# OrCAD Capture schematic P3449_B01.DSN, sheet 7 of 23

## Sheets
7 0016_HDMI: size Custom
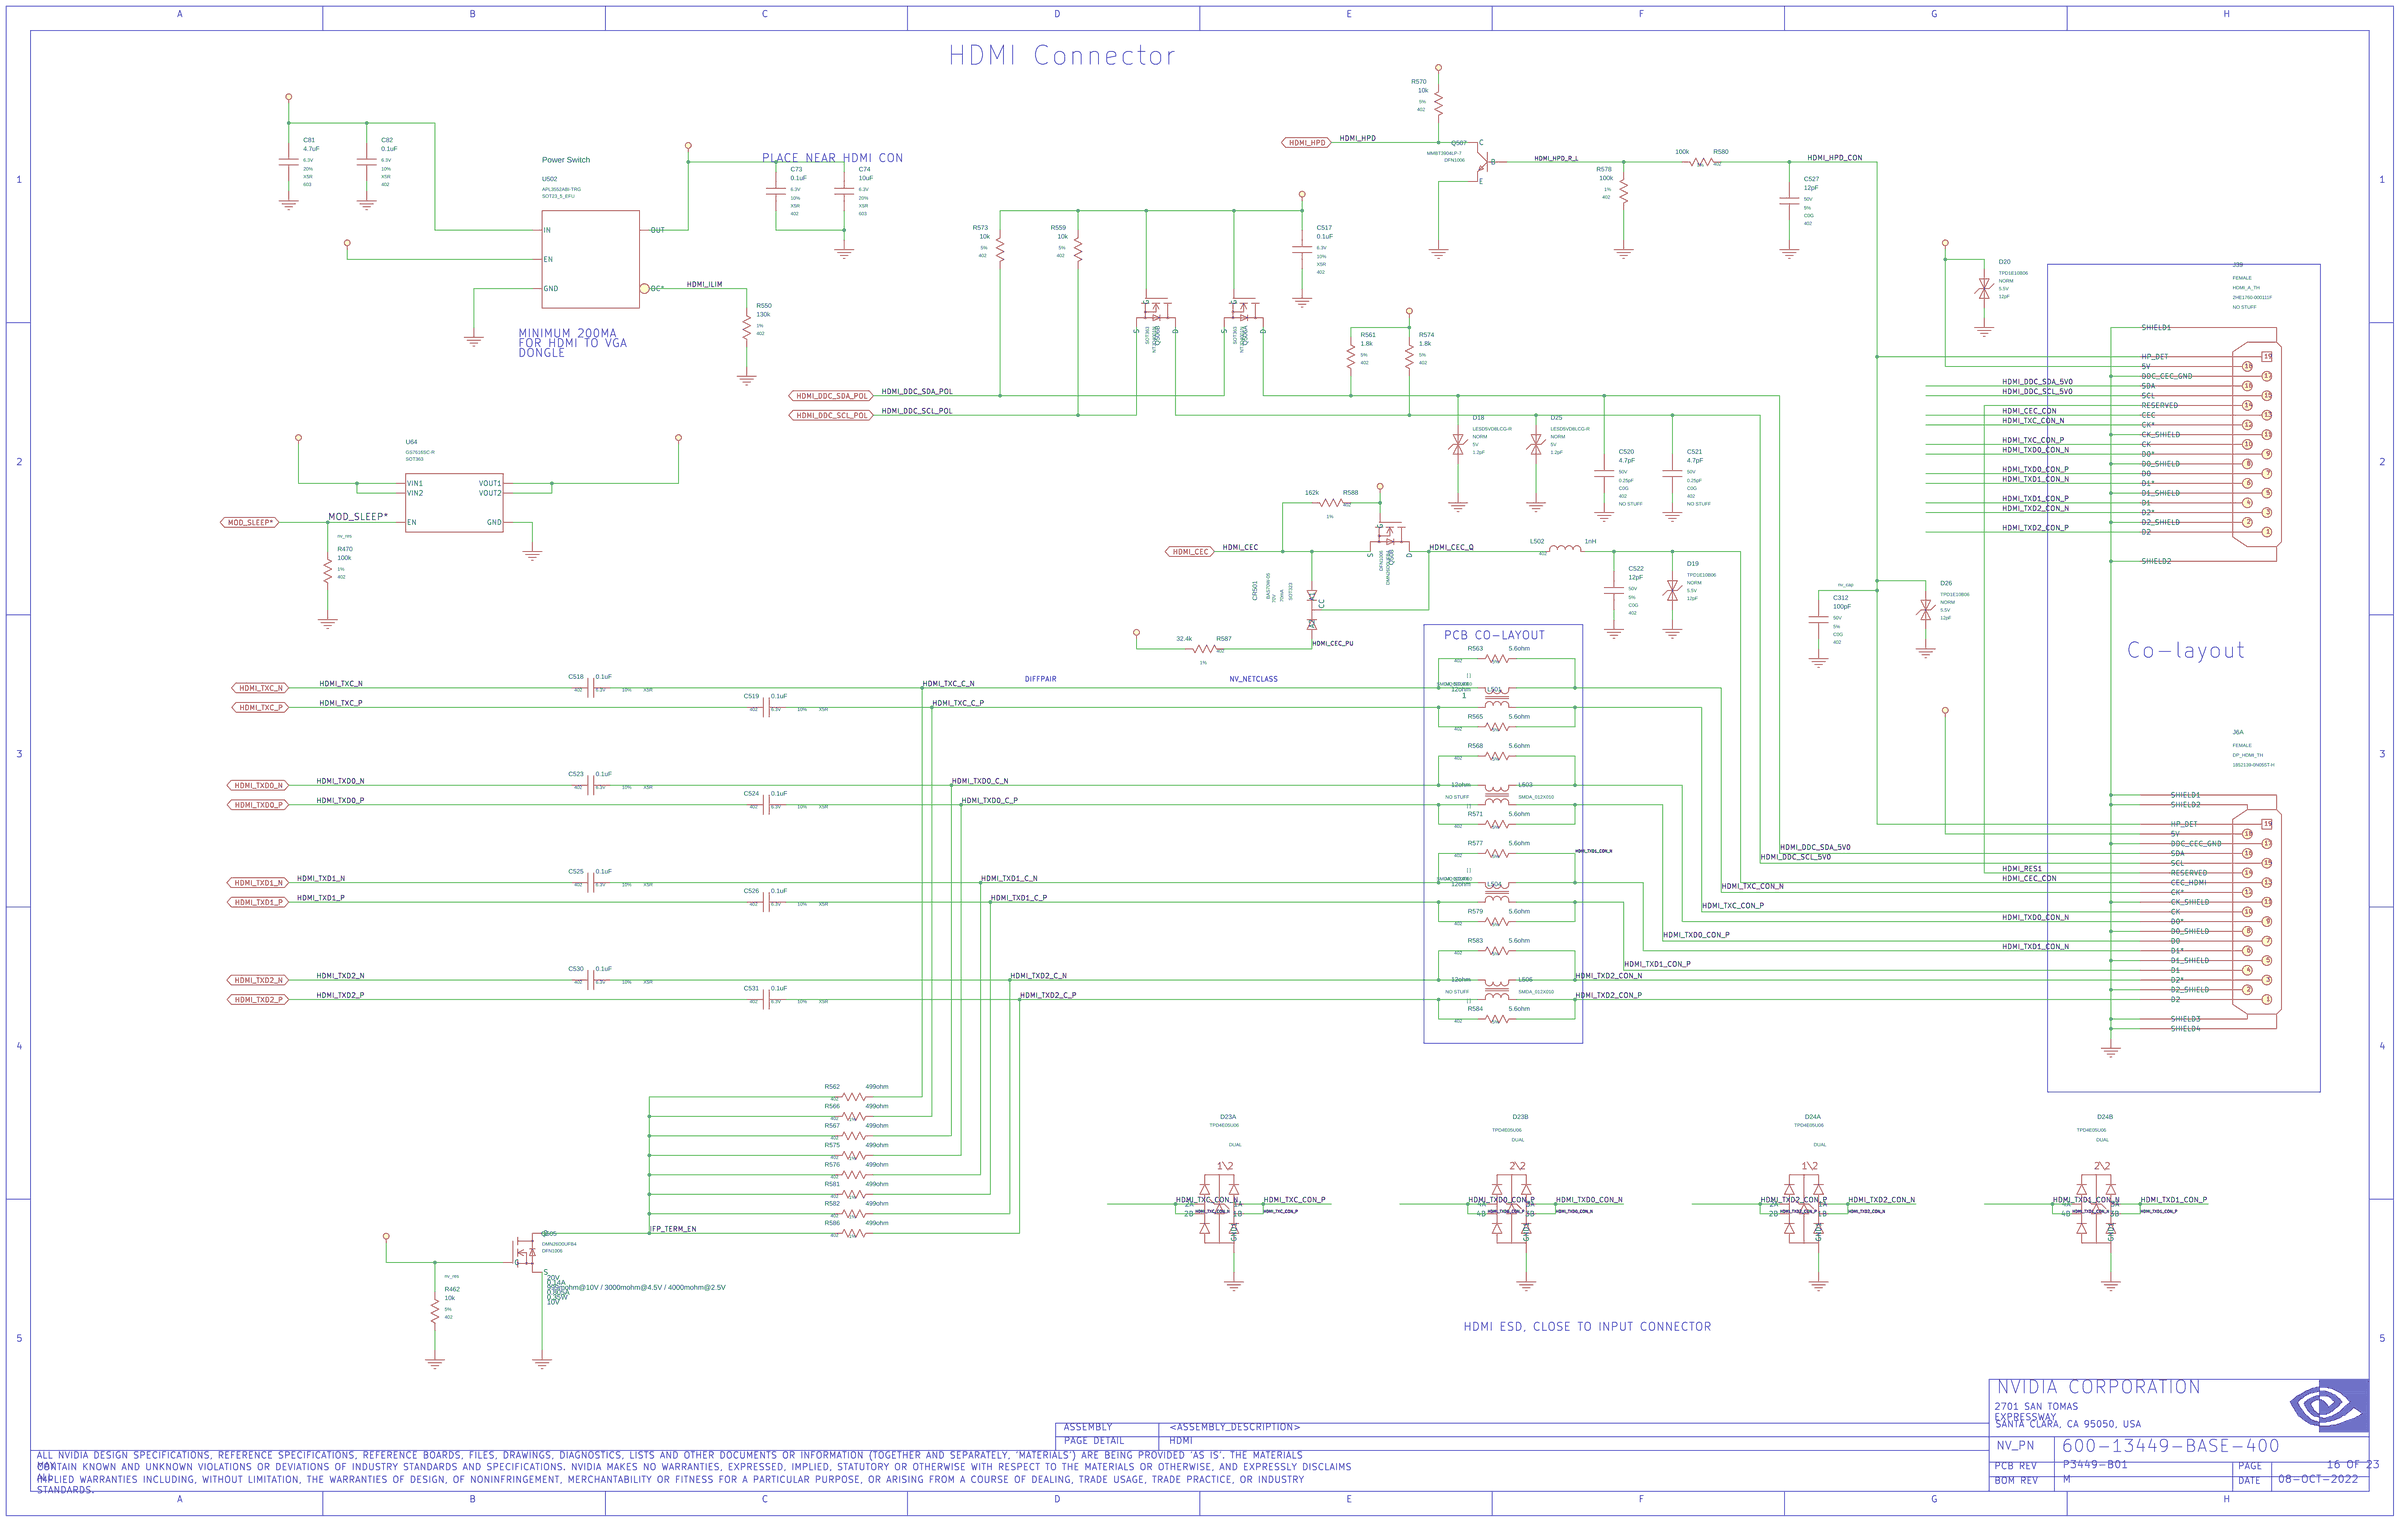
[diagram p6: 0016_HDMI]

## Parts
sheet 0016_HDMI
C73  0.1uF  [402]
C74  10uF  [603]
C81  4.7uF  [603]
C82  0.1uF  [402]
C312  100pF  [402]
C517  0.1uF  [402]
C518  0.1uF  [402]
C519  0.1uF  [402]
C520  4.7pF  [402]
C521  4.7pF  [402]
C522  12pF  [402]
C523  0.1uF  [402]
C524  0.1uF  [402]
C525  0.1uF  [402]
C526  0.1uF  [402]
C527  12pF  [402]
C530  0.1uF  [402]
C531  0.1uF  [402]
CR501  D_3PIN_CC  [SOT323]
D18  D_ESD  [DIODE_SMD_010X060]
D19  D_ESD  [DIODE_SMD_010X060]
D20  D_ESD  [DIODE_SMD_010X060]
D23  D_ESD_DIFFPAIR  [TSLP10_P050_025X010]  (sections A,B)
D24  D_ESD_DIFFPAIR  [TSLP10_P050_025X010]  (sections A,B)
D25  D_ESD  [DIODE_SMD_010X060]
D26  D_ESD  [DIODE_SMD_010X060]
J39  CON_HDMI  [CON_HDMI_019_TH_RA_F_P015]
L501  12ohm  [IND_NONRKO_SMD_012X010]
L502  1nH  [IND_SMD_0402]
L503  12ohm  [IND_NONRKO_SMD_012X010]
L504  12ohm  [IND_NONRKO_SMD_012X010]
L506  12ohm  [IND_NONRKO_SMD_012X010]
Q505  Q_FET_N_ENH  [DFET_003_SMD_010X006_B]
Q506  Q_FET_N_ENH  [SC70_6]  (sections A,B)
Q507  Q_NPN  [DFET_003_SMD_010X006_B]
Q508  Q_FET_N_ENH  [DFET_003_SMD_010X006_B]
R462  10k  [402]
R470  100k  [402]
R550  130k  [402]
R559  10k  [402]
R561  1.8k  [402]
R562  499ohm  [402]
R563  5.6ohm  [402]
R565  5.6ohm  [402]
R566  499ohm  [402]
R567  499ohm  [402]
R568  5.6ohm  [402]
R570  10k  [402]
R571  5.6ohm  [402]
R573  10k  [402]
R574  1.8k  [402]
R575  499ohm  [402]
R576  499ohm  [402]
R577  5.6ohm  [402]
R578  100k  [402]
R579  5.6ohm  [402]
R580  100k  [402]
R581  499ohm  [402]
R582  499ohm  [402]
R583  5.6ohm  [402]
R584  5.6ohm  [402]
R586  499ohm  [402]
R587  32.4k  [402]
R588  162k  [402]
U64  U_SW_LOAD  [SC70_6]
U502  U_PWR_SW_UL  [SOT23_5]
sheet 0017_DisplayPort
J6  CON_HDMI_DISPLAYPORT  [CON_HDMI_019_DP_020_TH_RA_F_181X180_B]  (sections A,B)

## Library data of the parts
C73 = C#1: ASSEMBLY: HDMI; CDS_LIB: discrete; CDS_PART_NAME: C_0402-0.1UF,X5R,10%,6.3V,039-0007-000; CDS_PHYS_PART_NAME: C_0402-0.1UF,X5R,10%,6.3V,039-0007-000-0.1UF,039-0007-000; CDS_SEC: 1; CHIPS_PART_NAME: C; DEVICE_TYPENAME: C_0402-01UFX5R1063V039-0007-000-01UF039-0007-000; DRAWING: @P3449_B01_LIB.P3449_B01(SCH_1):PAGE16; ESL: N/A; ESR: N/A; MAT: X5R; MAX_VOLTAGE: 6.3V; NV_PN: 039-0007-000; PATH: I332; PHYS_PAGE: 16; ROT: 0; SEC: 1; SIGNAL_MODEL: nv_cap; TOL: 10%; VER: 1; XY: (-8200,6650)
C74 = C#1: ASSEMBLY: HDMI; CDS_LIB: discrete; CDS_PART_NAME: C_0603-10UF,X5R,20%,6.3V,039-0135-000; CDS_PHYS_PART_NAME: C_0603-10UF,X5R,20%,6.3V,039-0135-000-039-0135-000,10UF; CDS_SEC: 1; CHIPS_PART_NAME: C; DEVICE_TYPENAME: C_0603-10UFX5R2063V039-0135-000-039-0135-00010UF; DRAWING: @P3449_B01_LIB.P3449_B01(SCH_1):PAGE16; ESL: N/A; ESR: N/A; MAT: X5R; MAX_VOLTAGE: 6.3V; NV_PN: 039-0135-000; PATH: I340; PHYS_PAGE: 16; ROT: 0; SEC: 1; SIGNAL_MODEL: nv_cap; TOL: 20%; VER: 1; XY: (-7850,6650)
C81 = C#1: ASSEMBLY: HDMI; CDS_LIB: discrete; CDS_PART_NAME: C_0603-4.7UF,X5R,20%,6.3V,032-0886-000; CDS_PHYS_PART_NAME: C_0603-4.7UF,X5R,20%,6.3V,032-0886-000-032-0886-000,4.7UF; CDS_SEC: 1; CHIPS_PART_NAME: C; DEVICE_TYPENAME: C_0603-47UFX5R2063V032-0886-000-032-0886-00047UF; DRAWING: @P3449_B01_LIB.P3449_B01(SCH_1):PAGE16; MAT: X5R; MAX_VOLTAGE: 6.3V; NV_PN: 032-0886-000; PATH: I266; PHYS_PAGE: 16; ROT: 0; SEC: 1; SIGNAL_MODEL: nv_cap; TOL: 20%; VER: 1; XY: (-10700,6800)
C82 = C#1: ASSEMBLY: HDMI; CDS_LIB: discrete; CDS_PART_NAME: C_0402-0.1UF,X5R,10%,6.3V,039-0007-000; CDS_PHYS_PART_NAME: C_0402-0.1UF,X5R,10%,6.3V,039-0007-000-0.1UF,039-0007-000; CDS_SEC: 1; CHIPS_PART_NAME: C; DEVICE_TYPENAME: C_0402-01UFX5R1063V039-0007-000-01UF039-0007-000; DRAWING: @P3449_B01_LIB.P3449_B01(SCH_1):PAGE16; ESL: N/A; ESR: N/A; MAT: X5R; MAX_VOLTAGE: 6.3V; NV_PN: 039-0007-000; PATH: I271; PHYS_PAGE: 16; ROT: 0; SEC: 1; SIGNAL_MODEL: nv_cap; TOL: 10%; VER: 1; XY: (-10300,6800)
C312 = C#1: ASSEMBLY: HDMI; CDS_LIB: discrete; CDS_PART_NAME: C_0402-100PF,C0G,5%,50V,035-0012-000; CDS_PHYS_PART_NAME: C_0402-100PF,C0G,5%,50V,035-0012-000-035-0012-000,100PF; CDS_SEC: 1; CHIPS_PART_NAME: C; DEVICE_TYPENAME: C_0402-100PFC0G550V035-0012-000-035-0012-000100PF; DRAWING: @P3449_B01_LIB.P3449_B01(SCH_1):PAGE16; MAT: C0G; MAX_VOLTAGE: 50V; NV_PN: 035-0012-000; PATH: I415; PHYS_PAGE: 16; ROT: 0; SEC: 1; SIGNAL_MODEL: nv_cap; TOL: 5%; VER: 1; XY: (-2850,4450)
C517 = C#1: ASSEMBLY: HDMI; CDS_LIB: discrete; CDS_PART_NAME: C_0402-0.1UF,X5R,10%,6.3V,039-0007-000; CDS_PHYS_PART_NAME: C_0402-0.1UF,X5R,10%,6.3V,039-0007-000-0.1UF,039-0007-000; CDS_SEC: 1; CHIPS_PART_NAME: C; DEVICE_TYPENAME: C_0402-01UFX5R1063V039-0007-000-01UF039-0007-000; DRAWING: @P3449_B01_LIB.P3449_B01(SCH_1):PAGE16; ESL: N/A; ESR: N/A; MAT: X5R; MAX_VOLTAGE: 6.3V; NV_PN: 039-0007-000; PATH: I315; PHYS_PAGE: 16; ROT: 0; SEC: 1; SIGNAL_MODEL: nv_cap; TOL: 10%; VER: 1; XY: (-5500,6350)
C518 = C: ASSEMBLY: HDMI; CDS_LIB: discrete; CDS_PART_NAME: C_0402-0.1UF,X5R,10%,6.3V,039-0007-000; CDS_PHYS_PART_NAME: C_0402-0.1UF,X5R,10%,6.3V,039-0007-000-0.1UF,039-0007-000; CDS_SEC: 1; DEVICE_TYPENAME: C_0402-01UFX5R1063V039-0007-000-01UF039-0007-000; DRAWING: @P3449_B01_LIB.P3449_B01(SCH_1):PAGE16; MAT: X5R; MAX_VOLTAGE: 6.3V; NO_XNET: 1; NV_PN: 039-0007-000; PATH: I259; PHYS_PAGE: 16; ROT: 0; SEC: 1; SIGNAL_MODEL: nv_cap; TOL: 10%; VER: 2; XY: (-9150,4100)
C519 = C: ASSEMBLY: HDMI; CDS_LIB: discrete; CDS_PART_NAME: C_0402-0.1UF,X5R,10%,6.3V,039-0007-000; CDS_PHYS_PART_NAME: C_0402-0.1UF,X5R,10%,6.3V,039-0007-000-0.1UF,039-0007-000; CDS_SEC: 1; DEVICE_TYPENAME: C_0402-01UFX5R1063V039-0007-000-01UF039-0007-000; DRAWING: @P3449_B01_LIB.P3449_B01(SCH_1):PAGE16; MAT: X5R; MAX_VOLTAGE: 6.3V; NO_XNET: 1; NV_PN: 039-0007-000; PATH: I260; PHYS_PAGE: 16; ROT: 0; SEC: 1; SIGNAL_MODEL: nv_cap; TOL: 10%; VER: 2; XY: (-8250,4000)
C520 = C#1: ASSEMBLY: HDMI; CDS_LIB: discrete; CDS_PART_NAME: C_0402-4.7PF,C0G,0.25PF,50V,035-0031-000; CDS_PHYS_PART_NAME: C_0402-4.7PF,C0G,0.25PF,50V,035-0031-000-035-0031-000,4.7PF; CDS_SEC: 1; CHIPS_PART_NAME: C; DEVICE_TYPENAME: C_0402-47PFC0G025PF50V035-0031-000-035-0031-00047PF; DRAWING: @P3449_B01_LIB.P3449_B01(SCH_1):PAGE16; MAT: C0G; MAX_VOLTAGE: 50V; NV_PN: 035-0031-000; PATH: I342; PHYS_PAGE: 16; ROT: 0; SEC: 1; SIGNAL_MODEL: nv_cap; SKU: NO STUFF; TOL: 0.25pF; VER: 1; XY: (-3950,5200)
C521 = C#1: ASSEMBLY: HDMI; CDS_LIB: discrete; CDS_PART_NAME: C_0402-4.7PF,C0G,0.25PF,50V,035-0031-000; CDS_PHYS_PART_NAME: C_0402-4.7PF,C0G,0.25PF,50V,035-0031-000-035-0031-000,4.7PF; CDS_SEC: 1; CHIPS_PART_NAME: C; DEVICE_TYPENAME: C_0402-47PFC0G025PF50V035-0031-000-035-0031-00047PF; DRAWING: @P3449_B01_LIB.P3449_B01(SCH_1):PAGE16; MAT: C0G; MAX_VOLTAGE: 50V; NV_PN: 035-0031-000; PATH: I344; PHYS_PAGE: 16; ROT: 0; SEC: 1; SIGNAL_MODEL: nv_cap; SKU: NO STUFF; TOL: 0.25pF; VER: 1; XY: (-3600,5200)
C522 = C#1: ASSEMBLY: HDMI; CDS_LIB: discrete; CDS_PART_NAME: C_0402-12PF,C0G,5%,50V,035-0014-000; CDS_PHYS_PART_NAME: C_0402-12PF,C0G,5%,50V,035-0014-000-035-0014-000,12PF; CDS_SEC: 1; CHIPS_PART_NAME: C; DEVICE_TYPENAME: C_0402-12PFC0G550V035-0014-000-035-0014-00012PF; DRAWING: @P3449_B01_LIB.P3449_B01(SCH_1):PAGE16; ESL: N/A; ESR: N/A; MAT: C0G; MAX_VOLTAGE: 50V; NV_PN: 035-0014-000; PATH: I330; PHYS_PAGE: 16; ROT: 0; SEC: 1; SIGNAL_MODEL: nv_cap; TOL: 5%; VER: 1; XY: (-3900,4600)
C523 = C: ASSEMBLY: HDMI; CDS_LIB: discrete; CDS_PART_NAME: C_0402-0.1UF,X5R,10%,6.3V,039-0007-000; CDS_PHYS_PART_NAME: C_0402-0.1UF,X5R,10%,6.3V,039-0007-000-0.1UF,039-0007-000; CDS_SEC: 1; DEVICE_TYPENAME: C_0402-01UFX5R1063V039-0007-000-01UF039-0007-000; DRAWING: @P3449_B01_LIB.P3449_B01(SCH_1):PAGE16; MAT: X5R; MAX_VOLTAGE: 6.3V; NO_XNET: 1; NV_PN: 039-0007-000; PATH: I258; PHYS_PAGE: 16; ROT: 0; SEC: 1; SIGNAL_MODEL: nv_cap; TOL: 10%; VER: 2; XY: (-9150,3600)
C524 = C: ASSEMBLY: HDMI; CDS_LIB: discrete; CDS_PART_NAME: C_0402-0.1UF,X5R,10%,6.3V,039-0007-000; CDS_PHYS_PART_NAME: C_0402-0.1UF,X5R,10%,6.3V,039-0007-000-0.1UF,039-0007-000; CDS_SEC: 1; DEVICE_TYPENAME: C_0402-01UFX5R1063V039-0007-000-01UF039-0007-000; DRAWING: @P3449_B01_LIB.P3449_B01(SCH_1):PAGE16; MAT: X5R; MAX_VOLTAGE: 6.3V; NO_XNET: 1; NV_PN: 039-0007-000; PATH: I255; PHYS_PAGE: 16; ROT: 0; SEC: 1; SIGNAL_MODEL: nv_cap; TOL: 10%; VER: 2; XY: (-8250,3500)
C525 = C: ASSEMBLY: HDMI; CDS_LIB: discrete; CDS_PART_NAME: C_0402-0.1UF,X5R,10%,6.3V,039-0007-000; CDS_PHYS_PART_NAME: C_0402-0.1UF,X5R,10%,6.3V,039-0007-000-0.1UF,039-0007-000; CDS_SEC: 1; DEVICE_TYPENAME: C_0402-01UFX5R1063V039-0007-000-01UF039-0007-000; DRAWING: @P3449_B01_LIB.P3449_B01(SCH_1):PAGE16; MAT: X5R; MAX_VOLTAGE: 6.3V; NO_XNET: 1; NV_PN: 039-0007-000; PATH: I254; PHYS_PAGE: 16; ROT: 0; SEC: 1; SIGNAL_MODEL: nv_cap; TOL: 10%; VER: 2; XY: (-9150,3100)
C526 = C: ASSEMBLY: HDMI; CDS_LIB: discrete; CDS_PART_NAME: C_0402-0.1UF,X5R,10%,6.3V,039-0007-000; CDS_PHYS_PART_NAME: C_0402-0.1UF,X5R,10%,6.3V,039-0007-000-0.1UF,039-0007-000; CDS_SEC: 1; DEVICE_TYPENAME: C_0402-01UFX5R1063V039-0007-000-01UF039-0007-000; DRAWING: @P3449_B01_LIB.P3449_B01(SCH_1):PAGE16; MAT: X5R; MAX_VOLTAGE: 6.3V; NO_XNET: 1; NV_PN: 039-0007-000; PATH: I256; PHYS_PAGE: 16; ROT: 0; SEC: 1; SIGNAL_MODEL: nv_cap; TOL: 10%; VER: 2; XY: (-8250,3000)
C527 = C#1: ASSEMBLY: HDMI; CDS_LIB: discrete; CDS_PART_NAME: C_0402-12PF,C0G,5%,50V,035-0014-000; CDS_PHYS_PART_NAME: C_0402-12PF,C0G,5%,50V,035-0014-000-035-0014-000,12PF; CDS_SEC: 1; CHIPS_PART_NAME: C; DEVICE_TYPENAME: C_0402-12PFC0G550V035-0014-000-035-0014-00012PF; DRAWING: @P3449_B01_LIB.P3449_B01(SCH_1):PAGE16; ESL: N/A; ESR: N/A; MAT: C0G; MAX_VOLTAGE: 50V; NV_PN: 035-0014-000; PATH: I357; PHYS_PAGE: 16; ROT: 0; SEC: 1; SIGNAL_MODEL: nv_cap; TOL: 5%; VER: 1; XY: (-3000,6600)
C530 = C: ASSEMBLY: HDMI; CDS_LIB: discrete; CDS_PART_NAME: C_0402-0.1UF,X5R,10%,6.3V,039-0007-000; CDS_PHYS_PART_NAME: C_0402-0.1UF,X5R,10%,6.3V,039-0007-000-0.1UF,039-0007-000; CDS_SEC: 1; DEVICE_TYPENAME: C_0402-01UFX5R1063V039-0007-000-01UF039-0007-000; DRAWING: @P3449_B01_LIB.P3449_B01(SCH_1):PAGE16; MAT: X5R; MAX_VOLTAGE: 6.3V; NO_XNET: 1; NV_PN: 039-0007-000; PATH: I253; PHYS_PAGE: 16; ROT: 0; SEC: 1; SIGNAL_MODEL: nv_cap; TOL: 10%; VER: 2; XY: (-9150,2600)
C531 = C: ASSEMBLY: HDMI; CDS_LIB: discrete; CDS_PART_NAME: C_0402-0.1UF,X5R,10%,6.3V,039-0007-000; CDS_PHYS_PART_NAME: C_0402-0.1UF,X5R,10%,6.3V,039-0007-000-0.1UF,039-0007-000; CDS_SEC: 1; DEVICE_TYPENAME: C_0402-01UFX5R1063V039-0007-000-01UF039-0007-000; DRAWING: @P3449_B01_LIB.P3449_B01(SCH_1):PAGE16; MAT: X5R; MAX_VOLTAGE: 6.3V; NO_XNET: 1; NV_PN: 039-0007-000; PATH: I257; PHYS_PAGE: 16; ROT: 0; SEC: 1; SIGNAL_MODEL: nv_cap; TOL: 10%; VER: 2; XY: (-8250,2500)
CR501 = D_3PIN_CC#1: ASSEMBLY: HDMI; CDS_LIB: discrete; CDS_PART_NAME: D_3PIN_CC_SOT323-BAS70W-05,1 PAIR - COMMON CATHODE,70V,0.1A,1V@15MA,70MA,091-0023-000; CDS_PHYS_PART_NAME: D_3PIN_CC_SOT323-BAS70W-05,1 PAIR - COMMON CATHODE,70V,0.1A,1V@15MA,70MA,091-0023-000-091-0023-000; CDS_SEC: 1; CONFIGURATION: 1 Pair - Common Cathode; CONTINUOUS_CURRENT: 70mA; DEVICE_TYPENAME: D_3PIN_CC_SOT323-BAS70W-051PAIR-COMMONCATHODE70V01A1V15MA70MA091-0023-000-091-0023-000; DRAWING: @P3449_B01_LIB.P3449_B01(SCH_1):PAGE16; FORWARD_VOLTAGE: 1V@15mA; MAX_CURRENT: 0.1A; MAX_VOLTAGE: 70V; NV_NAME: BAS70W-05; NV_PN: 091-0023-000; PATH: I291; PHYS_PAGE: 16; ROT: 1; SEC: 1; VER: 4; XY: (-5450,4500)
D18 = D_ESD: ASSEMBLY: HDMI; BREAKDOWN_VOLTAGE_MIN_TYP: 5.5V; CAPACITANCE_MAX_TYP: 1.2pF; CDS_LIB: discrete; CDS_PART_NAME: D_ESD_NORM-LESD5VD8LCG-R,1 LINE,BI-DIRECTIONAL,5V,0.05UA,5.5V,10V@2A,1.2PF,090-0172-000; CDS_PHYS_PART_NAME: D_ESD_NORM-LESD5VD8LCG-R,1 LINE,BI-DIRECTIONAL,5V,0.05UA,5.5V,10V@2A,1.2PF,090-0172-000-090-0172-000; CDS_SEC: 1; CLAMPING_VOLTAGE: 10V@2A; CONFIGURATION: 1 Line; DEVICE_TYPENAME: D_ESD_NORM-LESD5VD8LCG-R1LINEBI-DIRECTIONAL5V005UA55V10V2A12PF090-0172-000-090-0172-000; DRAWING: @P3449_B01_LIB.P3449_B01(SCH_1):PAGE16; MAX_REVERSE_LEAKAGE_CURRENT: 0.05uA; MAX_REVERSE_VOLTAGE: 5V; NV_NAME: LESD5VD8LCG-R; NV_PN: 090-0172-000; PACK_TYPE: NORM; PATH: I399; PHYS_PAGE: 16; POLARITY: Bi-Directional; ROT: 0; SEC: 1; SEC_TYPE: NORM; VER: 2; XY: (-4700,5350)
D19 = D_ESD: ASSEMBLY: HDMI; BREAKDOWN_VOLTAGE_MIN_TYP: 6V; CAPACITANCE_MAX_TYP: 12pF; CDS_LIB: discrete; CDS_PART_NAME: D_ESD_NORM-TPD1E10B06,1 LINE,BI-DIRECTIONAL,5.5V,0.1UA,6V,10V@1A,12PF,090-0243-000; CDS_PHYS_PART_NAME: D_ESD_NORM-TPD1E10B06,1 LINE,BI-DIRECTIONAL,5.5V,0.1UA,6V,10V@1A,12PF,090-0243-000-090-0243-000; CDS_SEC: 1; CLAMPING_VOLTAGE: 10V@1A; CONFIGURATION: 1 Line; DEVICE_TYPENAME: D_ESD_NORM-TPD1E10B061LINEBI-DIRECTIONAL55V01UA6V10V1A12PF090-0243-000-090-0243-000; DRAWING: @P3449_B01_LIB.P3449_B01(SCH_1):PAGE16; MAX_REVERSE_LEAKAGE_CURRENT: 0.1uA; MAX_REVERSE_VOLTAGE: 5.5V; NV_NAME: TPD1E10B06; NV_PN: 090-0243-000; PACK_TYPE: NORM; PATH: I400; PHYS_PAGE: 16; POLARITY: Bi-Directional; ROT: 0; SEC: 1; SEC_TYPE: NORM; VER: 2; XY: (-3600,4600)
D20 = D_ESD: ASSEMBLY: HDMI; BREAKDOWN_VOLTAGE_MIN_TYP: 6V; CAPACITANCE_MAX_TYP: 12pF; CDS_LIB: discrete; CDS_PART_NAME: D_ESD_NORM-TPD1E10B06,1 LINE,BI-DIRECTIONAL,5.5V,0.1UA,6V,10V@1A,12PF,090-0243-000; CDS_PHYS_PART_NAME: D_ESD_NORM-TPD1E10B06,1 LINE,BI-DIRECTIONAL,5.5V,0.1UA,6V,10V@1A,12PF,090-0243-000-090-0243-000; CDS_SEC: 1; CLAMPING_VOLTAGE: 10V@1A; CONFIGURATION: 1 Line; DEVICE_TYPENAME: D_ESD_NORM-TPD1E10B061LINEBI-DIRECTIONAL55V01UA6V10V1A12PF090-0243-000-090-0243-000; DRAWING: @P3449_B01_LIB.P3449_B01(SCH_1):PAGE16; MAX_REVERSE_LEAKAGE_CURRENT: 0.1uA; MAX_REVERSE_VOLTAGE: 5.5V; NV_NAME: TPD1E10B06; NV_PN: 090-0243-000; PACK_TYPE: NORM; PATH: I397; PHYS_PAGE: 16; POLARITY: Bi-Directional; ROT: 0; SEC: 1; SEC_TYPE: NORM; VER: 2; XY: (-2000,6150)
D23 = D_ESD_DIFFPAIR: ASSEMBLY: HDMI; BREAKDOWN_VOLTAGE_MIN_TYP: 6V; CAPACITANCE_MAX_TYP: 0.5pF; CDS_LIB: discrete; CDS_PART_NAME: D_ESD_DIFFPAIR_DUAL-TPD4E05U06,2 DIFFPAIR,UNI-DIRECTIONAL,5.5V,10UA,6V,10V@1A,0.5PF,090-0231-000; CDS_PHYS_PART_NAME: D_ESD_DIFFPAIR_DUAL-TPD4E05U06,2 DIFFPAIR,UNI-DIRECTIONAL,5.5V,10UA,6V,10V@1A,0.5PF,090-0231-000-090-0231-000; CDS_SEC: 1; CLAMPING_VOLTAGE: 10V@1A; CONFIGURATION: 2 Diffpair; CaptureCellPackProp: D_ESD_DIFFPAIRA; DEVICE_TYPENAME: D_ESD_DIFFPAIR_DUAL-TPD4E05U062DIFFPAIRUNI-DIRECTIONAL55V10UA6V10V1A05PF090-0231-000-090-0231-000; DRAWING: @P3449_B01_LIB.P3449_B01(SCH_1):PAGE16; MAX_REVERSE_LEAKAGE_CURRENT: 10uA; MAX_REVERSE_VOLTAGE: 5.5V; NV_NAME: TPD4E05U06; NV_PN: 090-0231-000; PACK_TYPE: DUAL; PATH: I403; PHYS_PAGE: 16; POLARITY: Uni-Directional; ROT: 2; SEC: 1; SEC_TYPE: DUAL; VER: 1; XY: (-5900,1450)
D24 = D_ESD_DIFFPAIR: ASSEMBLY: HDMI; BREAKDOWN_VOLTAGE_MIN_TYP: 6V; CAPACITANCE_MAX_TYP: 0.5pF; CDS_LIB: discrete; CDS_PART_NAME: D_ESD_DIFFPAIR_DUAL-TPD4E05U06,2 DIFFPAIR,UNI-DIRECTIONAL,5.5V,10UA,6V,10V@1A,0.5PF,090-0231-000; CDS_PHYS_PART_NAME: D_ESD_DIFFPAIR_DUAL-TPD4E05U06,2 DIFFPAIR,UNI-DIRECTIONAL,5.5V,10UA,6V,10V@1A,0.5PF,090-0231-000-090-0231-000; CDS_SEC: 1; CLAMPING_VOLTAGE: 10V@1A; CONFIGURATION: 2 Diffpair; CaptureCellPackProp: D_ESD_DIFFPAIRA; DEVICE_TYPENAME: D_ESD_DIFFPAIR_DUAL-TPD4E05U062DIFFPAIRUNI-DIRECTIONAL55V10UA6V10V1A05PF090-0231-000-090-0231-000; DRAWING: @P3449_B01_LIB.P3449_B01(SCH_1):PAGE16; MAX_REVERSE_LEAKAGE_CURRENT: 10uA; MAX_REVERSE_VOLTAGE: 5.5V; NV_NAME: TPD4E05U06; NV_PN: 090-0231-000; PACK_TYPE: DUAL; PATH: I405; PHYS_PAGE: 16; POLARITY: Uni-Directional; ROT: 2; SEC: 1; SEC_TYPE: DUAL; VER: 1; XY: (-2900,1450)
D25 = D_ESD: ASSEMBLY: HDMI; BREAKDOWN_VOLTAGE_MIN_TYP: 5.5V; CAPACITANCE_MAX_TYP: 1.2pF; CDS_LIB: discrete; CDS_PART_NAME: D_ESD_NORM-LESD5VD8LCG-R,1 LINE,BI-DIRECTIONAL,5V,0.05UA,5.5V,10V@2A,1.2PF,090-0172-000; CDS_PHYS_PART_NAME: D_ESD_NORM-LESD5VD8LCG-R,1 LINE,BI-DIRECTIONAL,5V,0.05UA,5.5V,10V@2A,1.2PF,090-0172-000-090-0172-000; CDS_SEC: 1; CLAMPING_VOLTAGE: 10V@2A; CONFIGURATION: 1 Line; DEVICE_TYPENAME: D_ESD_NORM-LESD5VD8LCG-R1LINEBI-DIRECTIONAL5V005UA55V10V2A12PF090-0172-000-090-0172-000; DRAWING: @P3449_B01_LIB.P3449_B01(SCH_1):PAGE16; MAX_REVERSE_LEAKAGE_CURRENT: 0.05uA; MAX_REVERSE_VOLTAGE: 5V; NV_NAME: LESD5VD8LCG-R; NV_PN: 090-0172-000; PACK_TYPE: NORM; PATH: I407; PHYS_PAGE: 16; POLARITY: Bi-Directional; ROT: 0; SEC: 1; VER: 2; XY: (-4300,5350)
D26 = D_ESD: ASSEMBLY: HDMI; BREAKDOWN_VOLTAGE_MIN_TYP: 6V; CAPACITANCE_MAX_TYP: 12pF; CDS_LIB: discrete; CDS_PART_NAME: D_ESD_NORM-TPD1E10B06,1 LINE,BI-DIRECTIONAL,5.5V,0.1UA,6V,10V@1A,12PF,090-0243-000; CDS_PHYS_PART_NAME: D_ESD_NORM-TPD1E10B06,1 LINE,BI-DIRECTIONAL,5.5V,0.1UA,6V,10V@1A,12PF,090-0243-000-090-0243-000; CDS_SEC: 1; CLAMPING_VOLTAGE: 10V@1A; CONFIGURATION: 1 Line; DEVICE_TYPENAME: D_ESD_NORM-TPD1E10B061LINEBI-DIRECTIONAL55V01UA6V10V1A12PF090-0243-000-090-0243-000; DRAWING: @P3449_B01_LIB.P3449_B01(SCH_1):PAGE16; MAX_REVERSE_LEAKAGE_CURRENT: 0.1uA; MAX_REVERSE_VOLTAGE: 5.5V; NV_NAME: TPD1E10B06; NV_PN: 090-0243-000; PACK_TYPE: NORM; PATH: I409; PHYS_PAGE: 16; POLARITY: Bi-Directional; ROT: 0; SEC: 1; VER: 2; XY: (-2300,4500)
J39 = CON_HDMI: ANGLE: 90; ASSEMBLY: HDMI; CDS_LIB: electro_mechanic; CDS_PART_NAME: CON_HDMI_HDMI_A_TH-2HE1760-000111F,FEMALE,1.5MM,90,YES,YES,YES,YES,YES,500 V,500 MA,064-0375-000; CDS_PHYS_PART_NAME: CON_HDMI_HDMI_A_TH-2HE1760-000111F,FEMALE,1.5MM,90,YES,YES,YES,YES,YES,500 V,500 MA,064-0375-000-064-0375-000; CDS_SEC: 1; DEVICE_TYPENAME: CON_HDMI_HDMI_A_TH-2HE1760-000111FFEMALE15MM90YESYESYESYESYES500V500MA064-0375-000-064-0375-000; DRAWING: @P3449_B01_LIB.P3449_B01(SCH_1):PAGE16; EMI_GROUND_TAB: YES; GENDER: FEMALE; LATCHING: YES; MAX_CURRENT: 500 mA; MAX_VOLTAGE: 500 V; NV_NAME: 2HE1760-000111F; NV_PN: 064-0375-000; PACK_TYPE: HDMI_A_TH; PATH: I393; PHYS_PAGE: 16; PITCH: 1.5mm; REFLOW: YES; ROT: 0; SEC: 1; SEC_TYPE: HDMI_A_TH; SHIELDED: YES; SHROUDED: YES; SKU: NO STUFF; VER: 4; XY: (-600,5350)
L501 = L_CMF_4P#1: ASSEMBLY: HDMI; CDS_LIB: discrete; CDS_PART_NAME: L_CMF_4P_SMDA_012X010-12OHM,[ ],25%,0.1A,1.5OHM,MCZ1210DH120L2TA0G,102-0066-000; CDS_PHYS_PART_NAME: L_CMF_4P_SMDA_012X010-12OHM,[ ],25%,0.1A,1.5OHM,MCZ1210DH120L2TA0G,102-0066-000-102-0066-000,12OHM; CDS_SEC: 1; CHIPS_PART_NAME: L_CMF_4P; DC_RESISTANCE: 1.5ohm; DEVICE_TYPENAME: L_CMF_4P_SMDA_012X010-12OHM2501A15OHMMCZ1210DH120L2TA0G102-0066-000-102-0066-00012OHM; DRAWING: @P3449_B01_LIB.P3449_B01(SCH_1):PAGE16; MAT: [ ]; MAX_CURRENT: 0.1A; NO_XNET_CONNECTION: 1; NV_NAME: MCZ1210DH120L2TA0G; NV_PN: 102-0066-000; PACK_TYPE: SMDA_012X010; PATH: I301; PHYS_PAGE: 16; PLACEMENT_NOTE: CoLayout with R563, R565; ROT: 4; SEC: 1; SEC_TYPE: SMDA_012X010; SIGNAL_MODEL: nv_ind_cmf_4p; SKU: NO STUFF; TOL: 25%; VER: 1; XY: (-4500,4050)
L502 = L: ACOUSTIC_MARGIN: [ ]; ASSEMBLY: HDMI; CDS_LIB: discrete; CDS_PART_NAME: L_0402-1NH,MULTI-LAYER,30%,0.4A,0.4A,0.07OHM,8@100MHZ,10GHZ,130-1041-000; CDS_PHYS_PART_NAME: L_0402-1NH,MULTI-LAYER,30%,0.4A,0.4A,0.07OHM,8@100MHZ,10GHZ,130-1041-000-130-1041-000,1NH; CDS_SEC: 1; CONTINUOUS_CURRENT: 0.4A; DC_RESISTANCE: 0.07ohm; DEVICE_TYPENAME: L_0402-1NHMULTI-LAYER3004A04A007OHM8100MHZ10GHZ130-1041-000-130-1041-0001NH; DRAWING: @P3449_B01_LIB.P3449_B01(SCH_1):PAGE16; MAT: multi-layer; MAX_CURRENT: 0.4A; NV_PN: 130-1041-000; PACK_TYPE: 402; PATH: I319; PHYS_PAGE: 16; Q: 8@100MHz; ROT: 0; SEC: 1; SELF_RESONANCE_FREQ: 10GHz; SIGNAL_MODEL: nv_ind; TOL: 30%; VER: 1; XY: (-4150,4800)
L503 = L_CMF_4P#1: ASSEMBLY: HDMI; CDS_LIB: discrete; CDS_PART_NAME: L_CMF_4P_SMDA_012X010-12OHM,[ ],25%,0.1A,1.5OHM,MCZ1210DH120L2TA0G,102-0066-000; CDS_PHYS_PART_NAME: L_CMF_4P_SMDA_012X010-12OHM,[ ],25%,0.1A,1.5OHM,MCZ1210DH120L2TA0G,102-0066-000-102-0066-000,12OHM; CDS_SEC: 1; CHIPS_PART_NAME: L_CMF_4P; DC_RESISTANCE: 1.5ohm; DEVICE_TYPENAME: L_CMF_4P_SMDA_012X010-12OHM2501A15OHMMCZ1210DH120L2TA0G102-0066-000-102-0066-00012OHM; DRAWING: @P3449_B01_LIB.P3449_B01(SCH_1):PAGE16; MAT: [ ]; MAX_CURRENT: 0.1A; NV_NAME: MCZ1210DH120L2TA0G; NV_PN: 102-0066-000; PACK_TYPE: SMDA_012X010; PATH: I298; PHYS_PAGE: 16; PLACEMENT_NOTE: CoLayout with R568, R571; ROT: 2; SEC: 1; SEC_TYPE: SMDA_012X010; SIGNAL_MODEL: nv_ind_cmf_4p; SKU: NO STUFF; TOL: 25%; VER: 1; XY: (-4500,3550)
L504 = L_CMF_4P#1: ASSEMBLY: HDMI; CDS_LIB: discrete; CDS_PART_NAME: L_CMF_4P_SMDA_012X010-12OHM,[ ],25%,0.1A,1.5OHM,MCZ1210DH120L2TA0G,102-0066-000; CDS_PHYS_PART_NAME: L_CMF_4P_SMDA_012X010-12OHM,[ ],25%,0.1A,1.5OHM,MCZ1210DH120L2TA0G,102-0066-000-102-0066-000,12OHM; CDS_SEC: 1; CHIPS_PART_NAME: L_CMF_4P; DC_RESISTANCE: 1.5ohm; DEVICE_TYPENAME: L_CMF_4P_SMDA_012X010-12OHM2501A15OHMMCZ1210DH120L2TA0G102-0066-000-102-0066-00012OHM; DRAWING: @P3449_B01_LIB.P3449_B01(SCH_1):PAGE16; MAT: [ ]; MAX_CURRENT: 0.1A; NV_NAME: MCZ1210DH120L2TA0G; NV_PN: 102-0066-000; PACK_TYPE: SMDA_012X010; PATH: I295; PHYS_PAGE: 16; PLACEMENT_NOTE: CoLayout with R577, R579; ROT: 4; SEC: 1; SEC_TYPE: SMDA_012X010; SIGNAL_MODEL: nv_ind_cmf_4p; SKU: NO STUFF; TOL: 25%; VER: 1; XY: (-4500,3050)
L506 = L_CMF_4P#1: ASSEMBLY: HDMI; CDS_LIB: discrete; CDS_PART_NAME: L_CMF_4P_SMDA_012X010-12OHM,[ ],25%,0.1A,1.5OHM,MCZ1210DH120L2TA0G,102-0066-000; CDS_PHYS_PART_NAME: L_CMF_4P_SMDA_012X010-12OHM,[ ],25%,0.1A,1.5OHM,MCZ1210DH120L2TA0G,102-0066-000-102-0066-000,12OHM; CDS_SEC: 1; CHIPS_PART_NAME: L_CMF_4P; DC_RESISTANCE: 1.5ohm; DEVICE_TYPENAME: L_CMF_4P_SMDA_012X010-12OHM2501A15OHMMCZ1210DH120L2TA0G102-0066-000-102-0066-00012OHM; DRAWING: @P3449_B01_LIB.P3449_B01(SCH_1):PAGE16; MAT: [ ]; MAX_CURRENT: 0.1A; NV_NAME: MCZ1210DH120L2TA0G; NV_PN: 102-0066-000; PACK_TYPE: SMDA_012X010; PATH: I293; PHYS_PAGE: 16; PLACEMENT_NOTE: CoLayout with R583, R584; ROT: 2; SEC: 1; SEC_TYPE: SMDA_012X010; SIGNAL_MODEL: nv_ind_cmf_4p; SKU: NO STUFF; TOL: 25%; VER: 1; XY: (-4500,2550)
Q505 = Q_FET_N_ENH#1: ASSEMBLY: HDMI; CDS_LIB: discrete; CDS_PART_NAME: Q_FET_N_ENH_DFN1006-DMN26D0UFB4,20V,999MOHM@10V / 3000MOHM@4.5V / 4000MOHM@2.5V,0.14A,0.805A,10V,0.35W,999NC@10V / 0NC@4.5V / A; CDS_PHYS_PART_NAME: Q_FET_N_ENH_DFN1006-DMN26D0UFB4,20V,999MOHM@10V / 3000MOHM@4.5V / 4000MOHM@2.5V,0.14A,0.805A,10V,0.35W,999NC@10V / 0NC@4.5V / B; CDS_SEC: 1; CONTINUOUS_CURRENT: 0.14A; CaptureCellPackProp: Q_FET_N_ENH##1; DEVICE_TYPENAME: Q_FET_N_ENH_DFN1006-DMN26D0UFB420V999MOHM10V3000MOHM45V4000MOHM25V014A0805A10V035W999NC10V0NC45VB; DRAWING: @P3449_B01_LIB.P3449_B01(SCH_1):PAGE16; MAX_CURRENT: 0.805A; MAX_VOLTAGE: 20V; MAX_WATTAGE: 0.35W; NV_NAME: DMN26D0UFB4; NV_PN: 300-0868-000; PACK_TYPE: DFN1006; PATH: I362; PHYS_PAGE: 16; Q_G: 999nC@10V / 0nC@4.5V / 999nC@2.5V; ROT: 0; R_DS_ON: 999mohm@10V / 3000mohm@4.5V / 4000mohm@2.5V; SEC: 1; VER: 2; V_BE_GS: 10V; XY: (-9500,1200)
Q506 = Q_FET_N_ENH: ASSEMBLY: HDMI; CDS_LIB: discrete; CDS_PART_NAME: Q_FET_N_ENH_SOT363-NTJD4001N,30V,1500MOHM@10V / 1500MOHM@4.5V / 1500MOHM@2.5V,0.25A,0.25A,20V,0.272W,[ ]@10V / [ ]@4.5V / [ ]@A; CDS_PHYS_PART_NAME: Q_FET_N_ENH_SOT363-NTJD4001N,30V,1500MOHM@10V / 1500MOHM@4.5V / 1500MOHM@2.5V,0.25A,0.25A,20V,0.272W,[ ]@10V / [ ]@4.5V / [ ]@B; CDS_SEC: 1; CONTINUOUS_CURRENT: 0.25A; DEVICE_TYPENAME: Q_FET_N_ENH_SOT363-NTJD4001N30V1500MOHM10V1500MOHM45V1500MOHM25V025A025A20V0272W10V45VB; DRAWING: @P3449_B01_LIB.P3449_B01(SCH_1):PAGE16; MAX_CURRENT: 0.25A; MAX_VOLTAGE: 30V; MAX_WATTAGE: 0.272W; NV_NAME: NTJD4001N; NV_PN: 300-0402-000; PACK_TYPE: SOT363; PATH: I312; PHYS_PAGE: 16; Q_G: [ ]@10V / [ ]@4.5V / [ ]@2.5V; ROT: 5; R_DS_ON: 1500mohm@10V / 1500mohm@4.5V / 1500mohm@2.5V; SEC: 1; SEC_TYPE: SOT363; VER: 2; V_BE_GS: 20V; XY: (-5800,6050)
Q507 = Q_NPN: ASSEMBLY: HDMI; CDS_LIB: discrete; CDS_PART_NAME: Q_NPN_DFN1006-MMBT3904LP-7,40V,0.3V,0.2A,9999A,6V,0.25W,300-0869-000; CDS_PHYS_PART_NAME: Q_NPN_DFN1006-MMBT3904LP-7,40V,0.3V,0.2A,9999A,6V,0.25W,300-0869-000-300-0869-000; CDS_SEC: 1; CONTINUOUS_CURRENT: 0.2A; DEVICE_TYPENAME: Q_NPN_DFN1006-MMBT3904LP-740V03V02A9999A6V025W300-0869-000-300-0869-000; DRAWING: @P3449_B01_LIB.P3449_B01(SCH_1):PAGE16; MAX_CURRENT: 9999A; MAX_VOLTAGE: 40V; MAX_WATTAGE: 0.25W; NV_NAME: MMBT3904LP-7; NV_PN: 300-0869-000; PACK_TYPE: DFN1006; PATH: I352; PHYS_PAGE: 16; ROT: 2; SEC: 1; VER: 1; V_BE_GS: 6V; V_CE_SAT: 0.3V; XY: (-4550,6800)
Q508 = Q_FET_N_ENH#1: ASSEMBLY: HDMI; CDS_LIB: discrete; CDS_PART_NAME: Q_FET_N_ENH_DFN1006-DMN26D0UFB4,20V,999MOHM@10V / 3000MOHM@4.5V / 4000MOHM@2.5V,0.14A,0.805A,10V,0.35W,999NC@10V / 0NC@4.5V / A; CDS_PHYS_PART_NAME: Q_FET_N_ENH_DFN1006-DMN26D0UFB4,20V,999MOHM@10V / 3000MOHM@4.5V / 4000MOHM@2.5V,0.14A,0.805A,10V,0.35W,999NC@10V / 0NC@4.5V / B; CDS_SEC: 1; CONTINUOUS_CURRENT: 0.14A; CaptureCellPackProp: Q_FET_N_ENH##1; DEVICE_TYPENAME: Q_FET_N_ENH_DFN1006-DMN26D0UFB420V999MOHM10V3000MOHM45V4000MOHM25V014A0805A10V035W999NC10V0NC45VB; DRAWING: @P3449_B01_LIB.P3449_B01(SCH_1):PAGE16; MAX_CURRENT: 0.805A; MAX_VOLTAGE: 20V; MAX_WATTAGE: 0.35W; NV_NAME: DMN26D0UFB4; NV_PN: 300-0868-000; PACK_TYPE: DFN1006; PATH: I317; PHYS_PAGE: 16; Q_G: 999nC@10V / 0nC@4.5V / 999nC@2.5V; ROT: 5; R_DS_ON: 999mohm@10V / 3000mohm@4.5V / 4000mohm@2.5V; SEC: 1; VER: 2; V_BE_GS: 10V; XY: (-5050,4900)
R462 = R: ASSEMBLY: HDMI; CDS_LIB: discrete; CDS_PART_NAME: R_0402-10K,5 %,62.5MW,195-0486-000; CDS_PHYS_PART_NAME: R_0402-10K,5 %,62.5MW,195-0486-000-10K,195-0486-000; CDS_SEC: 1; DEVICE_TYPENAME: R_0402-10K5625MW195-0486-000-10K195-0486-000; DRAWING: @P3449_B01_LIB.P3449_B01(SCH_1):PAGE16; MAX_WATTAGE: 62.5mW; NV_PN: 195-0486-000; PATH: I418; PHYS_PAGE: 16; ROT: 0; SEC: 1; SIGNAL_MODEL: nv_res; TOL: 5%; VER: 2; XY: (-9950,900)
R470 = R: ASSEMBLY: HDMI; CDS_LIB: discrete; CDS_PART_NAME: R_0402-100K,1 %,62.5MW,195-0005-000; CDS_PHYS_PART_NAME: R_0402-100K,1 %,62.5MW,195-0005-000-100K,195-0005-000; CDS_SEC: 1; DEVICE_TYPENAME: R_0402-100K1625MW195-0005-000-100K195-0005-000; DRAWING: @P3449_B01_LIB.P3449_B01(SCH_1):PAGE16; MAX_WATTAGE: 62.5mW; NV_PN: 195-0005-000; PATH: I424; PHYS_PAGE: 16; ROT: 0; SEC: 1; SIGNAL_MODEL: nv_res; TOL: 1%; VER: 2; XY: (-10500,4700)
R550 = R: ASSEMBLY: HDMI; CDS_LIB: discrete; CDS_PART_NAME: R_0402-130K,1 %,62.5MW,195-0061-000; CDS_PHYS_PART_NAME: R_0402-130K,1 %,62.5MW,195-0061-000-130K,195-0061-000; CDS_SEC: 1; DEVICE_TYPENAME: R_0402-130K1625MW195-0061-000-130K195-0061-000; DRAWING: @P3449_B01_LIB.P3449_B01(SCH_1):PAGE16; MAX_WATTAGE: 62.5mW; NV_PN: 195-0061-000; PATH: I274; PHYS_PAGE: 16; ROT: 0; SEC: 1; SIGNAL_MODEL: nv_res; TOL: 1%; VER: 2; XY: (-8350,5950)
R559 = R: ASSEMBLY: HDMI; CDS_LIB: discrete; CDS_PART_NAME: R_0402-10K,5 %,62.5MW,195-0486-000; CDS_PHYS_PART_NAME: R_0402-10K,5 %,62.5MW,195-0486-000-10K,195-0486-000; CDS_SEC: 1; DEVICE_TYPENAME: R_0402-10K5625MW195-0486-000-10K195-0486-000; DRAWING: @P3449_B01_LIB.P3449_B01(SCH_1):PAGE16; MAX_WATTAGE: 62.5mW; NV_PN: 195-0486-000; PATH: I308; PHYS_PAGE: 16; ROT: 2; SEC: 1; SIGNAL_MODEL: nv_res; TOL: 5%; VER: 2; XY: (-6650,6350)
R561 = R: ASSEMBLY: HDMI; CDS_LIB: discrete; CDS_PART_NAME: R_0402-1.8K,5 %,62.5MW,195-0528-000; CDS_PHYS_PART_NAME: R_0402-1.8K,5 %,62.5MW,195-0528-000-1.8K,195-0528-000; CDS_SEC: 1; DEVICE_TYPENAME: R_0402-18K5625MW195-0528-000-18K195-0528-000; DRAWING: @P3449_B01_LIB.P3449_B01(SCH_1):PAGE16; MAX_WATTAGE: 62.5mW; NV_PN: 195-0528-000; PATH: I321; PHYS_PAGE: 16; ROT: 0; SEC: 1; SIGNAL_MODEL: nv_res; TOL: 5%; VER: 2; XY: (-5250,5800)
R562 = R#1: ASSEMBLY: HDMI; CDS_LIB: discrete; CDS_PART_NAME: R_0402-499OHM,1 %,62.5MW,195-0338-000; CDS_PHYS_PART_NAME: R_0402-499OHM,1 %,62.5MW,195-0338-000-195-0338-000,499OHM; CDS_SEC: 1; CHIPS_PART_NAME: R; DEVICE_TYPENAME: R_0402-499OHM1625MW195-0338-000-195-0338-000499OHM; DRAWING: @P3449_B01_LIB.P3449_B01(SCH_1):PAGE16; MAX_WATTAGE: 62.5mW; NO_XNET_CONNECTION: 1; NV_PN: 195-0338-000; PATH: I283; PHYS_PAGE: 16; ROT: 0; SEC: 1; SIGNAL_MODEL: nv_res; TOL: 1%; VER: 1; XY: (-7800,2000)
R563 = R#1: ASSEMBLY: HDMI; CDS_LIB: discrete; CDS_PART_NAME: R_0402-5.6OHM,5 %,62.5MW,195-0609-000; CDS_PHYS_PART_NAME: R_0402-5.6OHM,5 %,62.5MW,195-0609-000-195-0609-000,5.6OHM; CDS_SEC: 1; CHIPS_PART_NAME: R; DEVICE_TYPENAME: R_0402-56OHM5625MW195-0609-000-195-0609-00056OHM; DRAWING: @P3449_B01_LIB.P3449_B01(SCH_1):PAGE16; MAX_WATTAGE: 62.5mW; NV_PN: 195-0609-000; PATH: I302; PHYS_PAGE: 16; PLACEMENT_NOTE: CoLayout with L501; ROT: 0; SEC: 1; SIGNAL_MODEL: nv_res; TOL: 5%; VER: 1; XY: (-4500,4250)
R565 = R#1: ASSEMBLY: HDMI; CDS_LIB: discrete; CDS_PART_NAME: R_0402-5.6OHM,5 %,62.5MW,195-0609-000; CDS_PHYS_PART_NAME: R_0402-5.6OHM,5 %,62.5MW,195-0609-000-195-0609-000,5.6OHM; CDS_SEC: 1; CHIPS_PART_NAME: R; DEVICE_TYPENAME: R_0402-56OHM5625MW195-0609-000-195-0609-00056OHM; DRAWING: @P3449_B01_LIB.P3449_B01(SCH_1):PAGE16; MAX_WATTAGE: 62.5mW; NV_PN: 195-0609-000; PATH: I300; PHYS_PAGE: 16; PLACEMENT_NOTE: CoLayout with L501; ROT: 0; SEC: 1; SIGNAL_MODEL: nv_res; TOL: 5%; VER: 1; XY: (-4500,3900)
R566 = R#1: ASSEMBLY: HDMI; CDS_LIB: discrete; CDS_PART_NAME: R_0402-499OHM,1 %,62.5MW,195-0338-000; CDS_PHYS_PART_NAME: R_0402-499OHM,1 %,62.5MW,195-0338-000-195-0338-000,499OHM; CDS_SEC: 1; CHIPS_PART_NAME: R; DEVICE_TYPENAME: R_0402-499OHM1625MW195-0338-000-195-0338-000499OHM; DRAWING: @P3449_B01_LIB.P3449_B01(SCH_1):PAGE16; MAX_WATTAGE: 62.5mW; NO_XNET_CONNECTION: 1; NV_PN: 195-0338-000; PATH: I282; PHYS_PAGE: 16; ROT: 0; SEC: 1; SIGNAL_MODEL: nv_res; TOL: 1%; VER: 1; XY: (-7800,1900)
R567 = R#1: ASSEMBLY: HDMI; CDS_LIB: discrete; CDS_PART_NAME: R_0402-499OHM,1 %,62.5MW,195-0338-000; CDS_PHYS_PART_NAME: R_0402-499OHM,1 %,62.5MW,195-0338-000-195-0338-000,499OHM; CDS_SEC: 1; CHIPS_PART_NAME: R; DEVICE_TYPENAME: R_0402-499OHM1625MW195-0338-000-195-0338-000499OHM; DRAWING: @P3449_B01_LIB.P3449_B01(SCH_1):PAGE16; MAX_WATTAGE: 62.5mW; NO_XNET_CONNECTION: 1; NV_PN: 195-0338-000; PATH: I281; PHYS_PAGE: 16; ROT: 0; SEC: 1; SIGNAL_MODEL: nv_res; TOL: 1%; VER: 1; XY: (-7800,1800)
R568 = R#1: ASSEMBLY: HDMI; CDS_LIB: discrete; CDS_PART_NAME: R_0402-5.6OHM,5 %,62.5MW,195-0609-000; CDS_PHYS_PART_NAME: R_0402-5.6OHM,5 %,62.5MW,195-0609-000-195-0609-000,5.6OHM; CDS_SEC: 1; CHIPS_PART_NAME: R; DEVICE_TYPENAME: R_0402-56OHM5625MW195-0609-000-195-0609-00056OHM; DRAWING: @P3449_B01_LIB.P3449_B01(SCH_1):PAGE16; MAX_WATTAGE: 62.5mW; NV_PN: 195-0609-000; PATH: I299; PHYS_PAGE: 16; PLACEMENT_NOTE: CoLayout with L503; ROT: 0; SEC: 1; SIGNAL_MODEL: nv_res; TOL: 5%; VER: 1; XY: (-4500,3750)
R570 = R: ASSEMBLY: HDMI; CDS_LIB: discrete; CDS_PART_NAME: R_0402-10K,5 %,62.5MW,195-0486-000; CDS_PHYS_PART_NAME: R_0402-10K,5 %,62.5MW,195-0486-000-10K,195-0486-000; CDS_SEC: 1; DEVICE_TYPENAME: R_0402-10K5625MW195-0486-000-10K195-0486-000; DRAWING: @P3449_B01_LIB.P3449_B01(SCH_1):PAGE16; MAX_WATTAGE: 62.5mW; NV_PN: 195-0486-000; PATH: I351; PHYS_PAGE: 16; ROT: 2; SEC: 1; SIGNAL_MODEL: nv_res; TOL: 5%; VER: 2; XY: (-4800,7100)
R571 = R#1: ASSEMBLY: HDMI; CDS_LIB: discrete; CDS_PART_NAME: R_0402-5.6OHM,5 %,62.5MW,195-0609-000; CDS_PHYS_PART_NAME: R_0402-5.6OHM,5 %,62.5MW,195-0609-000-195-0609-000,5.6OHM; CDS_SEC: 1; CHIPS_PART_NAME: R; DEVICE_TYPENAME: R_0402-56OHM5625MW195-0609-000-195-0609-00056OHM; DRAWING: @P3449_B01_LIB.P3449_B01(SCH_1):PAGE16; MAX_WATTAGE: 62.5mW; NV_PN: 195-0609-000; PATH: I297; PHYS_PAGE: 16; PLACEMENT_NOTE: CoLayout with L503; ROT: 0; SEC: 1; SIGNAL_MODEL: nv_res; TOL: 5%; VER: 1; XY: (-4500,3400)
R573 = R: ASSEMBLY: HDMI; CDS_LIB: discrete; CDS_PART_NAME: R_0402-10K,5 %,62.5MW,195-0486-000; CDS_PHYS_PART_NAME: R_0402-10K,5 %,62.5MW,195-0486-000-10K,195-0486-000; CDS_SEC: 1; DEVICE_TYPENAME: R_0402-10K5625MW195-0486-000-10K195-0486-000; DRAWING: @P3449_B01_LIB.P3449_B01(SCH_1):PAGE16; MAX_WATTAGE: 62.5mW; NV_PN: 195-0486-000; PATH: I306; PHYS_PAGE: 16; ROT: 2; SEC: 1; SIGNAL_MODEL: nv_res; TOL: 5%; VER: 2; XY: (-7050,6350)
R574 = R: ASSEMBLY: HDMI; CDS_LIB: discrete; CDS_PART_NAME: R_0402-1.8K,5 %,62.5MW,195-0528-000; CDS_PHYS_PART_NAME: R_0402-1.8K,5 %,62.5MW,195-0528-000-1.8K,195-0528-000; CDS_SEC: 1; DEVICE_TYPENAME: R_0402-18K5625MW195-0528-000-18K195-0528-000; DRAWING: @P3449_B01_LIB.P3449_B01(SCH_1):PAGE16; MAX_WATTAGE: 62.5mW; NV_PN: 195-0528-000; PATH: I323; PHYS_PAGE: 16; ROT: 0; SEC: 1; SIGNAL_MODEL: nv_res; TOL: 5%; VER: 2; XY: (-4950,5800)
R575 = R#1: ASSEMBLY: HDMI; CDS_LIB: discrete; CDS_PART_NAME: R_0402-499OHM,1 %,62.5MW,195-0338-000; CDS_PHYS_PART_NAME: R_0402-499OHM,1 %,62.5MW,195-0338-000-195-0338-000,499OHM; CDS_SEC: 1; CHIPS_PART_NAME: R; DEVICE_TYPENAME: R_0402-499OHM1625MW195-0338-000-195-0338-000499OHM; DRAWING: @P3449_B01_LIB.P3449_B01(SCH_1):PAGE16; MAX_WATTAGE: 62.5mW; NO_XNET_CONNECTION: 1; NV_PN: 195-0338-000; PATH: I280; PHYS_PAGE: 16; ROT: 0; SEC: 1; SIGNAL_MODEL: nv_res; TOL: 1%; VER: 1; XY: (-7800,1700)
R576 = R#1: ASSEMBLY: HDMI; CDS_LIB: discrete; CDS_PART_NAME: R_0402-499OHM,1 %,62.5MW,195-0338-000; CDS_PHYS_PART_NAME: R_0402-499OHM,1 %,62.5MW,195-0338-000-195-0338-000,499OHM; CDS_SEC: 1; CHIPS_PART_NAME: R; DEVICE_TYPENAME: R_0402-499OHM1625MW195-0338-000-195-0338-000499OHM; DRAWING: @P3449_B01_LIB.P3449_B01(SCH_1):PAGE16; MAX_WATTAGE: 62.5mW; NO_XNET_CONNECTION: 1; NV_PN: 195-0338-000; PATH: I279; PHYS_PAGE: 16; ROT: 0; SEC: 1; SIGNAL_MODEL: nv_res; TOL: 1%; VER: 1; XY: (-7800,1600)
R577 = R#1: ASSEMBLY: HDMI; CDS_LIB: discrete; CDS_PART_NAME: R_0402-5.6OHM,5 %,62.5MW,195-0609-000; CDS_PHYS_PART_NAME: R_0402-5.6OHM,5 %,62.5MW,195-0609-000-195-0609-000,5.6OHM; CDS_SEC: 1; CHIPS_PART_NAME: R; DEVICE_TYPENAME: R_0402-56OHM5625MW195-0609-000-195-0609-00056OHM; DRAWING: @P3449_B01_LIB.P3449_B01(SCH_1):PAGE16; MAX_WATTAGE: 62.5mW; NV_PN: 195-0609-000; PATH: I296; PHYS_PAGE: 16; PLACEMENT_NOTE: CoLayout with L504; ROT: 0; SEC: 1; SIGNAL_MODEL: nv_res; TOL: 5%; VER: 1; XY: (-4500,3250)
R578 = R: ASSEMBLY: HDMI; CDS_LIB: discrete; CDS_PART_NAME: R_0402-100K,1 %,62.5MW,195-0005-000; CDS_PHYS_PART_NAME: R_0402-100K,1 %,62.5MW,195-0005-000-100K,195-0005-000; CDS_SEC: 1; DEVICE_TYPENAME: R_0402-100K1625MW195-0005-000-100K195-0005-000; DRAWING: @P3449_B01_LIB.P3449_B01(SCH_1):PAGE16; MAX_WATTAGE: 62.5mW; NV_PN: 195-0005-000; PATH: I347; PHYS_PAGE: 16; ROT: 2; SEC: 1; SIGNAL_MODEL: nv_res; TOL: 1%; VER: 2; XY: (-3850,6650)
R579 = R#1: ASSEMBLY: HDMI; CDS_LIB: discrete; CDS_PART_NAME: R_0402-5.6OHM,5 %,62.5MW,195-0609-000; CDS_PHYS_PART_NAME: R_0402-5.6OHM,5 %,62.5MW,195-0609-000-195-0609-000,5.6OHM; CDS_SEC: 1; CHIPS_PART_NAME: R; DEVICE_TYPENAME: R_0402-56OHM5625MW195-0609-000-195-0609-00056OHM; DRAWING: @P3449_B01_LIB.P3449_B01(SCH_1):PAGE16; MAX_WATTAGE: 62.5mW; NV_PN: 195-0609-000; PATH: I294; PHYS_PAGE: 16; PLACEMENT_NOTE: CoLayout with L504; ROT: 0; SEC: 1; SIGNAL_MODEL: nv_res; TOL: 5%; VER: 1; XY: (-4500,2900)
R580 = R#1: ASSEMBLY: HDMI; CDS_LIB: discrete; CDS_PART_NAME: R_0402-100K,1 %,62.5MW,195-0005-000; CDS_PHYS_PART_NAME: R_0402-100K,1 %,62.5MW,195-0005-000-100K,195-0005-000; CDS_SEC: 1; CHIPS_PART_NAME: R; DEVICE_TYPENAME: R_0402-100K1625MW195-0005-000-100K195-0005-000; DRAWING: @P3449_B01_LIB.P3449_B01(SCH_1):PAGE16; MAX_WATTAGE: 62.5mW; NV_PN: 195-0005-000; PATH: I354; PHYS_PAGE: 16; ROT: 2; SEC: 1; SIGNAL_MODEL: nv_res; TOL: 1%; VER: 1; XY: (-3450,6800)
R581 = R#1: ASSEMBLY: HDMI; CDS_LIB: discrete; CDS_PART_NAME: R_0402-499OHM,1 %,62.5MW,195-0338-000; CDS_PHYS_PART_NAME: R_0402-499OHM,1 %,62.5MW,195-0338-000-195-0338-000,499OHM; CDS_SEC: 1; CHIPS_PART_NAME: R; DEVICE_TYPENAME: R_0402-499OHM1625MW195-0338-000-195-0338-000499OHM; DRAWING: @P3449_B01_LIB.P3449_B01(SCH_1):PAGE16; MAX_WATTAGE: 62.5mW; NO_XNET_CONNECTION: 1; NV_PN: 195-0338-000; PATH: I278; PHYS_PAGE: 16; ROT: 0; SEC: 1; SIGNAL_MODEL: nv_res; TOL: 1%; VER: 1; XY: (-7800,1500)
R582 = R#1: ASSEMBLY: HDMI; CDS_LIB: discrete; CDS_PART_NAME: R_0402-499OHM,1 %,62.5MW,195-0338-000; CDS_PHYS_PART_NAME: R_0402-499OHM,1 %,62.5MW,195-0338-000-195-0338-000,499OHM; CDS_SEC: 1; CHIPS_PART_NAME: R; DEVICE_TYPENAME: R_0402-499OHM1625MW195-0338-000-195-0338-000499OHM; DRAWING: @P3449_B01_LIB.P3449_B01(SCH_1):PAGE16; MAX_WATTAGE: 62.5mW; NO_XNET_CONNECTION: 1; NV_PN: 195-0338-000; PATH: I277; PHYS_PAGE: 16; ROT: 0; SEC: 1; SIGNAL_MODEL: nv_res; TOL: 1%; VER: 1; XY: (-7800,1400)
R583 = R#1: ASSEMBLY: HDMI; CDS_LIB: discrete; CDS_PART_NAME: R_0402-5.6OHM,5 %,62.5MW,195-0609-000; CDS_PHYS_PART_NAME: R_0402-5.6OHM,5 %,62.5MW,195-0609-000-195-0609-000,5.6OHM; CDS_SEC: 1; CHIPS_PART_NAME: R; DEVICE_TYPENAME: R_0402-56OHM5625MW195-0609-000-195-0609-00056OHM; DRAWING: @P3449_B01_LIB.P3449_B01(SCH_1):PAGE16; MAX_WATTAGE: 62.5mW; NV_PN: 195-0609-000; PATH: I292; PHYS_PAGE: 16; PLACEMENT_NOTE: CoLayout with L506; ROT: 0; SEC: 1; SIGNAL_MODEL: nv_res; TOL: 5%; VER: 1; XY: (-4500,2750)
R584 = R#1: ASSEMBLY: HDMI; CDS_LIB: discrete; CDS_PART_NAME: R_0402-5.6OHM,5 %,62.5MW,195-0609-000; CDS_PHYS_PART_NAME: R_0402-5.6OHM,5 %,62.5MW,195-0609-000-195-0609-000,5.6OHM; CDS_SEC: 1; CHIPS_PART_NAME: R; DEVICE_TYPENAME: R_0402-56OHM5625MW195-0609-000-195-0609-00056OHM; DRAWING: @P3449_B01_LIB.P3449_B01(SCH_1):PAGE16; MAX_WATTAGE: 62.5mW; NV_PN: 195-0609-000; PATH: I289; PHYS_PAGE: 16; PLACEMENT_NOTE: CoLayout with L506; ROT: 0; SEC: 1; SIGNAL_MODEL: nv_res; TOL: 5%; VER: 1; XY: (-4500,2400)
R586 = R#1: ASSEMBLY: HDMI; CDS_LIB: discrete; CDS_PART_NAME: R_0402-499OHM,1 %,62.5MW,195-0338-000; CDS_PHYS_PART_NAME: R_0402-499OHM,1 %,62.5MW,195-0338-000-195-0338-000,499OHM; CDS_SEC: 1; CHIPS_PART_NAME: R; DEVICE_TYPENAME: R_0402-499OHM1625MW195-0338-000-195-0338-000499OHM; DRAWING: @P3449_B01_LIB.P3449_B01(SCH_1):PAGE16; MAX_WATTAGE: 62.5mW; NO_XNET_CONNECTION: 1; NV_PN: 195-0338-000; PATH: I276; PHYS_PAGE: 16; ROT: 0; SEC: 1; SIGNAL_MODEL: nv_res; TOL: 1%; VER: 1; XY: (-7800,1300)
R587 = R#1: ASSEMBLY: HDMI; CDS_LIB: discrete; CDS_PART_NAME: R_0402-32.4K,1 %,62.5MW,195-0250-000; CDS_PHYS_PART_NAME: R_0402-32.4K,1 %,62.5MW,195-0250-000-195-0250-000,32.4K; CDS_SEC: 1; CHIPS_PART_NAME: R; DEVICE_TYPENAME: R_0402-324K1625MW195-0250-000-195-0250-000324K; DRAWING: @P3449_B01_LIB.P3449_B01(SCH_1):PAGE16; MAX_WATTAGE: 62.5mW; NV_PN: 195-0250-000; PATH: I290; PHYS_PAGE: 16; ROT: 2; SEC: 1; SIGNAL_MODEL: nv_res; TOL: 1%; VER: 1; XY: (-6000,4300)
R588 = R#1: ASSEMBLY: HDMI; CDS_LIB: discrete; CDS_PART_NAME: R_0402-162K,1 %,62.5MW,195-0106-000; CDS_PHYS_PART_NAME: R_0402-162K,1 %,62.5MW,195-0106-000-162K,195-0106-000; CDS_SEC: 1; CHIPS_PART_NAME: R; DEVICE_TYPENAME: R_0402-162K1625MW195-0106-000-162K195-0106-000; DRAWING: @P3449_B01_LIB.P3449_B01(SCH_1):PAGE16; MAX_WATTAGE: 62.5mW; NV_PN: 195-0106-000; PATH: I311; PHYS_PAGE: 16; ROT: 2; SEC: 1; SIGNAL_MODEL: nv_res; TOL: 1%; VER: 1; XY: (-5350,5050)
U64 = U_SW_LOAD: ASSEMBLY: HDMI; CDS_LIB: analog; CDS_PART_NAME: U_SW_LOAD_SOT363-GS7616SC-R,-9999V..9999V,-9999V..9999V,9999A,SWITCH,115-1566-000; CDS_PHYS_PART_NAME: U_SW_LOAD_SOT363-GS7616SC-R,-9999V..9999V,-9999V..9999V,9999A,SWITCH,115-1566-000-115-1566-000; CDS_SEC: 1; DEVICE_TYPENAME: U_SW_LOAD_SOT363-GS7616SC-R-9999V9999V-9999V9999V9999ASWITCH115-1566-000-115-1566-000; DRAWING: @P3449_B01_LIB.P3449_B01(SCH_1):PAGE16; MAX_CURRENT: 9999A; MAX_VOLTAGE: -9999V..9999V; NV_NAME: GS7616SC-R; NV_PN: 115-1566-000; OUTPUT_VOLTAGE: -9999V..9999V; PACK_TYPE: SOT363; PATH: I420; PHYS_PAGE: 16; ROT: 0; SEC: 1; TYPE: Switch; VER: 4; XY: (-9850,5050)
U502 = U_PWR_SW_UL: ASSEMBLY: HDMI; CDS_LIB: power_supply; CDS_PART_NAME: U_PWR_SW_UL_SOT23_5_EFU-APL3552ABI-TRG,2.7V..5.5V,2.7V..5.5V,2A,SWITCH,315-1062-000; CDS_PHYS_PART_NAME: U_PWR_SW_UL_SOT23_5_EFU-APL3552ABI-TRG,2.7V..5.5V,2.7V..5.5V,2A,SWITCH,315-1062-000-315-1062-000; CDS_SEC: 1; DEVICE_TYPENAME: U_PWR_SW_UL_SOT23_5_EFU-APL3552ABI-TRG27V55V27V55V2ASWITCH315-1062-000-315-1062-000; DRAWING: @P3449_B01_LIB.P3449_B01(SCH_1):PAGE16; FUNCTION: Power Switch; MAX_CURRENT: 2A; MAX_VOLTAGE: 2.7V..5.5V; NV_NAME: APL3552ABI-TRG; NV_PN: 315-1062-000; OUTPUT_VOLTAGE: 2.7V..5.5V; PACK_TYPE: SOT23_5_EFU; PATH: I273; PHYS_PAGE: 16; ROT: 0; SEC: 1; TYPE: Switch; VER: 1; XY: (-9150,6300)
J6 = CON_HDMI_DISPLAYPORT: ANGLE: 90; ASSEMBLY: HDMI; CDS_LIB: electro_mechanic; CDS_PART_NAME: CON_HDMI_DISPLAYPORT_DP_HDMI_TH-2HE1700-000111F,FEMALE,1.4MM,90,YES,YES,YES,YES,YES,40 MV,500 MA,064-0374-000; CDS_PHYS_PART_NAME: CON_HDMI_DISPLAYPORT_DP_HDMI_TH-2HE1700-000111F,FEMALE,1.4MM,90,YES,YES,YES,YES,YES,40 MV,500 MA,064-0374-000-064-0374-000; CDS_SEC: 1; CaptureCellPackProp: CON_HDMI_DISPLAYPORTA; DEVICE_TYPENAME: CON_HDMI_DISPLAYPORT_DP_HDMI_TH-2HE1700-000111FFEMALE14MM90YESYESYESYESYES40MV500MA064-0374-000-064-0374-000; DRAWING: @P3449_B01_LIB.P3449_B01(SCH_1):PAGE16; EMI_GROUND_TAB: YES; GENDER: FEMALE; LATCHING: YES; MAX_CURRENT: 500 mA; MAX_VOLTAGE: 40 mV; NV_NAME: 1852139-0N055T-H; NV_PN: 064-0374-000; PACK_TYPE: DP_HDMI_TH; PATH: I389; PHYS_PAGE: 16; PITCH: 1.4mm; REFLOW: YES; ROT: 0; SEC: 1; SHIELDED: YES; SHROUDED: YES; VER: 1; XY: (-600,2950)

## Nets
GND: C73.2 C74.2 C81.2 C82.2 C312.2 C517.2 C520.2 C521.2 C522.2 C527.2 D18.2 D19.2 D20.2 D23.3(GND1) D24.3(GND1) D25.2 D26.2 J6.2(D2_SHIELD) J6.5(D1_SHIELD) J6.8(D0_SHIELD) J6.11(CK_SHIELD) J6.17(DDC_CEC_GND) J6.40(SHIELD4) J6.41(SHIELD2) J6.42(SHIELD3) J6.43(SHIELD1) J39.2(D2_SHIELD) J39.5(D1_SHIELD) J39.8(D0_SHIELD) J39.11(CK_SHIELD) J39.17(DDC_CEC_GND) J39.20(SHIELD1) J39.21(SHIELD2) Q505.2(S) Q507.2(E) R462.2 R470.2 R550.2 R578.2 U64.4(GND) U502.2(GND) ; also on sheet 1 3 4 5 6 8 9 10 11 12 13 14 15 16 19
VDD_1V8: R570.1 ; also on sheet 3 4 6 9 11 19
VDD_3V3_HDMI: C517.1 Q505.1(G) Q506.2(G) Q506.5(G) Q508.1(G) R462.1 R559.1 R573.1 R587.2 R588.1 U64.1(VOUT1) U64.2(VOUT2) U502.4(EN)
VDD_3V3_SYS: U64.5(VIN1) U64.6(VIN2) ; also on sheet 3 4 5 6 8 9 11 18 19
VDD_5V0_HDMI_CON: C73.1 C74.1 D20.1 J6.18(5V) J39.18(5V) R561.1 R574.1 U502.1(OUT)
VDD_5V_IN: C81.1 C82.1 U502.5(IN) ; also on sheet 3 4 10 11 12 14 15 19
HDMI_CEC: CR501.1(A1) Q508.2(S) R588.2 ; also on sheet 17
HDMI_CEC_CON: C522.1 D19.1 J6.13(CEC_HDMI) J39.13(CEC) L502.2
HDMI_CEC_PU: CR501.2(A2) R587.1
HDMI_CEC_Q: CR501.3(CC) L502.1 Q508.3(D)
HDMI_DDC_SCL_5V0: C521.1 D25.1 J6.15(SCL) J39.15(SCL) Q506.3(D) R574.2
HDMI_DDC_SCL_POL: Q506.4(S) R559.2 ; also on sheet 17
HDMI_DDC_SDA_5V0: C520.1 D18.1 J6.16(SDA) J39.16(SDA) Q506.6(D) R561.2
HDMI_DDC_SDA_POL: Q506.1(S) R573.2 ; also on sheet 17
HDMI_HPD: Q507.3(C) R570.2 ; also on sheet 17
HDMI_HPD_CON: C312.1 C527.1 D26.1 J6.19(HP_DET) J39.19(HP_DET) R580.1
HDMI_HPD_R_L: Q507.1(B) R578.1 R580.2
HDMI_ILIM: R550.1 U502.3(OC*)
HDMI_RES1: J6.14(RESERVED) J39.14(RESERVED)
HDMI_TXC_C_N: C518.2 L501.3 R562.2 R563.1
HDMI_TXC_C_P: C519.2 L501.4 R565.1 R566.2
HDMI_TXC_CON_N: D23.2(2A) D23.9(2B) J6.12(CK*) J39.12(CK*) L501.2 R563.2
HDMI_TXC_CON_P: D23.1(1A) D23.10(1B) J6.10(CK) J39.10(CK) L501.1 R565.2
HDMI_TXC_N: C518.1 ; also on sheet 17
HDMI_TXC_P: C519.1 ; also on sheet 17
HDMI_TXD0_C_N: C523.2 L503.4 R567.2 R568.1
HDMI_TXD0_C_P: C524.2 L503.3 R571.1 R575.2
HDMI_TXD0_CON_N: D23.4(3A) D23.7(3B) J6.9(D0*) J39.9(D0*) L503.1 R568.2
HDMI_TXD0_CON_P: D23.5(4A) D23.6(4B) J6.7(D0) J39.7(D0) L503.2 R571.2
HDMI_TXD0_N: C523.1 ; also on sheet 17
HDMI_TXD0_P: C524.1 ; also on sheet 17
HDMI_TXD1_C_N: C525.2 L504.3 R576.2 R577.1
HDMI_TXD1_C_P: C526.2 L504.4 R579.1 R581.2
HDMI_TXD1_CON_N: D24.5(4A) D24.6(4B) J6.6(D1*) J39.6(D1*) L504.2 R577.2
HDMI_TXD1_CON_P: D24.4(3A) D24.7(3B) J6.4(D1) J39.4(D1) L504.1 R579.2
HDMI_TXD1_N: C525.1 ; also on sheet 17
HDMI_TXD1_P: C526.1 ; also on sheet 17
HDMI_TXD2_C_N: C530.2 L506.4 R582.2 R583.1
HDMI_TXD2_C_P: C531.2 L506.3 R584.1 R586.2
HDMI_TXD2_CON_N: D24.1(1A) D24.10(1B) J6.3(D2*) J39.3(D2*) L506.1 R583.2
HDMI_TXD2_CON_P: D24.2(2A) D24.9(2B) J6.1(D2) J39.1(D2) L506.2 R584.2
HDMI_TXD2_N: C530.1 ; also on sheet 17
HDMI_TXD2_P: C531.1 ; also on sheet 17
IFP_TERM_EN: Q505.3(D) R562.1 R566.1 R567.1 R575.1 R576.1 R581.1 R582.1 R586.1
MOD_SLEEP*: R470.1 U64.3(EN) ; also on sheet 3 19

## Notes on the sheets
sheet 7
- A
- B
- C
- D
- E
- F
- G
- H
- HDMI Connector
- PLACE NEAR HDMI CON
- 1
- 1
- MINIMUM 200MA
- FOR HDMI TO VGA
- DONGLE
- 2
- 2
- PCB CO-LAYOUT
- Co-layout
- DIFFPAIR
- NV_NETCLASS
- 3
- 3
- 4
- 4
- HDMI ESD, CLOSE TO INPUT CONNECTOR
- 5
- 5
- NVIDIA CORPORATION
- 2701 SAN TOMAS
  EXPRESSWAY
- ASSEMBLY
- <ASSEMBLY_DESCRIPTION>
- SANTA CLARA, CA 95050, USA
- PAGE DETAIL
- HDMI
- NV_PN
- 600-13449-BASE-400
- ALL NVIDIA DESIGN SPECIFICATIONS, REFERENCE SPECIFICATIONS, REFERENCE BOARDS, FILES, DRAWINGS, DIAGNOSTICS, LISTS AND OTHER DOCUMENTS OR INFORMATION (TOGETHER AND SEPARATELY, 'MATERIALS') ARE BEING PROVIDED 'AS IS'. THE MATERIALS
  MAY
- CONTAIN KNOWN AND UNKNOWN VIOLATIONS OR DEVIATIONS OF INDUSTRY STANDARDS AND SPECIFICATIONS. NVIDIA MAKES NO WARRANTIES, EXPRESSED, IMPLIED, STATUTORY OR OTHERWISE WITH RESPECT TO THE MATERIALS OR OTHERWISE, AND EXPRESSLY DISCLAIMS
  ALL
- PCB REV
- P3449-B01
- PAGE
- 16 OF 23
- IMPLIED WARRANTIES INCLUDING, WITHOUT LIMITATION, THE WARRANTIES OF DESIGN, OF NONINFRINGEMENT, MERCHANTABILITY OR FITNESS FOR A PARTICULAR PURPOSE, OR ARISING FROM A COURSE OF DEALING, TRADE USAGE, TRADE PRACTICE, OR INDUSTRY
  STANDARDS.
- BOM REV
- M
- DATE
- 08-OCT-2022
- A
- B
- C
- D
- E
- F
- G
- H
